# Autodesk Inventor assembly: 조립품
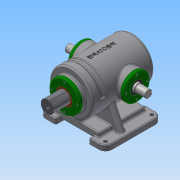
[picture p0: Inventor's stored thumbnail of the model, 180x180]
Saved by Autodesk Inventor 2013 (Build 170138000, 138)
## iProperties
Created: 2018-06
Part Number: 조립품
Document SubType Name: Assembly
Designer: Administrator
Author: Administrator
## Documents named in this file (13)
- C:\Users\Administrator\Desktop\380628V1013\답안조립품.iam
- C:\Users\Administrator\Desktop\380628V1013\본체.ipt
- C:\Users\Administrator\Desktop\380628V1013\가변스프링.ipt
- C:\Users\Administrator\Desktop\380628V1013\베어링 6205.ipt
- 베어링 6205.ipt
- C:\Users\Administrator\Desktop\380628V1013\볼트 M4.ipt
- C:\Users\Administrator\Desktop\380628V1013\부시.ipt
- C:\Users\Administrator\Desktop\380628V1013\슬라이드 커버.ipt
- C:\Users\Administrator\Desktop\380628V1013\슬라이드.ipt
- C:\Users\Administrator\Desktop\380628V1013\오일실.ipt
- 오일실.ipt
- C:\Users\Administrator\Desktop\380628V1013\축 커버.ipt
- C:\Users\Administrator\Desktop\380628V1013\편심축.ipt
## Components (1 placed, 1 different names)
1. 가변스프링:1
